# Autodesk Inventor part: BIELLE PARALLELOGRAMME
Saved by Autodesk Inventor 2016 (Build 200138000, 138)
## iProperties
Created: 2013-10
Part Number: BIELLE PARALLELOGRAMME
Material: solidworks materials|Alliage 1060
Document SubType Name: Modeling
Designer: Bruno
Density: 2.7 g/cm^3
Appearance: 229,234,237
Sending System: SolidWorks 2013
Last Author: christophe
Last Saved: 2014-02-15
Author: Bruno
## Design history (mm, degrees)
feature "Enlèv. mat.-Extru.1"
sketch "Esquisse1"
  geometry: 1 further point
  constraints: 1 other
node "Solide1"
